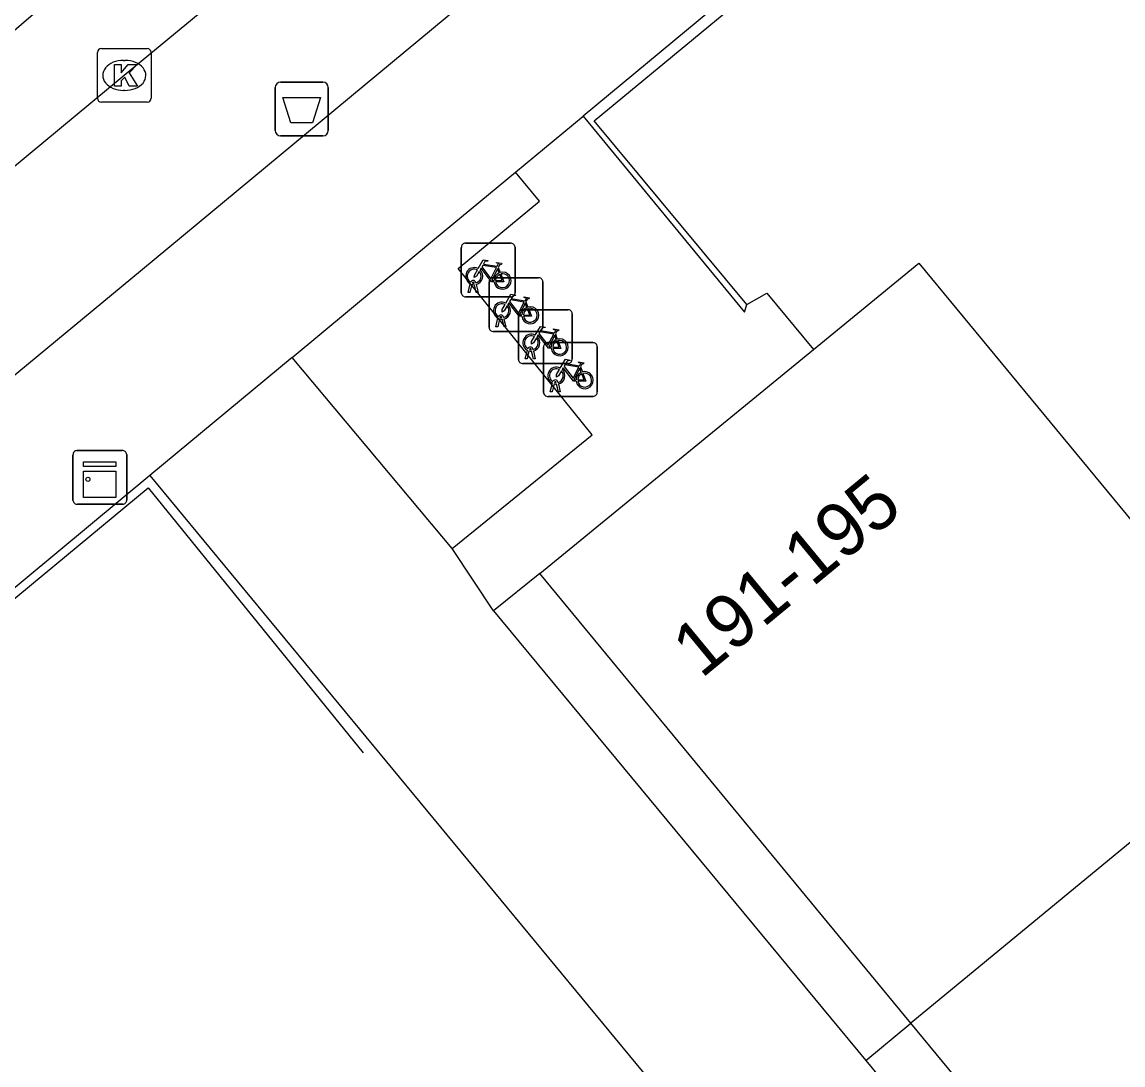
# Model space of a CAD drawing. Extents: x 162347 to 162868, y 381221 to 381813.
# Drawn here: x 162449.62 to 162470.1, y 381728.86 to 381748.27 of the extents above; entities that cross this region are included whole.
import ezdxf

# ---------------------------------------------------------------- set-up
doc = ezdxf.new("R2010")
doc.units = 0
for name, color, linetype in [('IMGEO_Afvalbak', 7, 'Continuous'), ('IMGEO_Fietsenrek', 7, 'Continuous'), ('IMGEO_Fietspad_open', 7, 'Continuous'), ('IMGEO_Hek', 7, 'Continuous'), ('IMGEO_Kast', 7, 'Continuous'), ('IMGEO_Kolk', 7, 'Continuous'), ('IMGEO_Pand', 7, 'Continuous'), ('IMGEO_Pand_nummerreeks', 7, 'Continuous'), ('IMGEO_Rijbaan_lokaal_open', 7, 'Continuous'), ('IMGEO_Voetpad_open', 7, 'Continuous')]:
    doc.layers.add(name, color=color, linetype=linetype)

msp = doc.modelspace()

# ---------------------------------------------------------------- linework, layer by layer
at = {"layer": 'IMGEO_Afvalbak'}
for p, q in [((162454.327, 381746.247), (162454.327, 381747.047)), ((162454.327, 381747.047), (162454.327, 381746.247)), ((162454.427, 381747.147), (162455.217, 381747.147)), ((162455.217, 381747.147), (162454.427, 381747.147)), ((162455.317, 381747.047), (162455.317, 381746.247)), ((162455.317, 381746.247), (162455.317, 381747.047)), ((162455.217, 381746.147), (162454.427, 381746.147)), ((162454.427, 381746.147), (162455.217, 381746.147))]:
    msp.add_line(p, q, dxfattribs=at)
msp.add_lwpolyline([(162454.47, 381746.861), (162455.174, 381746.861), (162455.025, 381746.391), (162454.619, 381746.391), (162454.47, 381746.861)], dxfattribs=at)
for centre, start, end in [((162454.427, 381747.047), 90, 180), ((162454.427, 381747.047), 90, 180), ((162455.217, 381747.047), 0, 90), ((162455.217, 381747.047), 360, 90), ((162454.427, 381746.247), 180, 270), ((162454.427, 381746.247), 180, 270), ((162455.217, 381746.247), 270, 0), ((162455.217, 381746.247), 270, 0)]:
    msp.add_arc(centre, 0.1, start, end, dxfattribs=at)
at = {"layer": 'IMGEO_Fietsenrek'}
for p, q in [((162457.792, 381743.226), (162457.792, 381744.067)), ((162457.792, 381744.067), (162457.792, 381743.226)), ((162457.867, 381744.151), (162458.708, 381744.151)), ((162458.708, 381744.151), (162457.867, 381744.151)), ((162458.792, 381744.076), (162458.792, 381743.235)), ((162458.792, 381743.235), (162458.792, 381744.076)), ((162458.479, 381743.7), (162458.515, 381743.605)), ((162457.919, 381743.235), (162457.958, 381743.395)), ((162457.988, 381743.383), (162457.953, 381743.235)), ((162458.03, 381743.407), (162458.029, 381743.411)), ((162458.071, 381743.235), (162458.037, 381743.377)), ((162458.061, 381743.418), (162458.062, 381743.411)), ((162458.069, 381743.381), (162458.104, 381743.235)), ((162458.308, 381742.583), (162458.308, 381743.424)), ((162458.308, 381743.424), (162458.308, 381742.583)), ((162458.383, 381743.508), (162459.224, 381743.508)), ((162459.224, 381743.508), (162458.383, 381743.508)), ((162459.308, 381743.433), (162459.308, 381742.592)), ((162459.308, 381742.592), (162459.308, 381743.433)), ((162458.717, 381743.151), (162457.876, 381743.151)), ((162457.876, 381743.151), (162458.717, 381743.151)), ((162457.953, 381743.235), (162457.919, 381743.235)), ((162458.104, 381743.235), (162458.071, 381743.235)), ((162458.995, 381743.057), (162459.031, 381742.962)), ((162458.435, 381742.592), (162458.474, 381742.752)), ((162458.504, 381742.74), (162458.469, 381742.592)), ((162458.546, 381742.764), (162458.545, 381742.768)), ((162458.577, 381742.775), (162458.578, 381742.768)), ((162458.855, 381741.987), (162458.855, 381742.828)), ((162458.855, 381742.828), (162458.855, 381741.987)), ((162458.93, 381742.912), (162459.771, 381742.912)), ((162459.771, 381742.912), (162458.93, 381742.912)), ((162459.855, 381742.837), (162459.855, 381741.996)), ((162459.855, 381741.996), (162459.855, 381742.837)), ((162458.469, 381742.592), (162458.435, 381742.592)), ((162458.587, 381742.592), (162458.553, 381742.734)), ((162458.585, 381742.738), (162458.62, 381742.592)), ((162458.62, 381742.592), (162458.587, 381742.592)), ((162459.233, 381742.508), (162458.392, 381742.508)), ((162458.392, 381742.508), (162459.233, 381742.508)), ((162459.542, 381742.461), (162459.578, 381742.366)), ((162458.982, 381741.996), (162459.021, 381742.156)), ((162459.051, 381742.144), (162459.016, 381741.996)), ((162459.093, 381742.168), (162459.092, 381742.172)), ((162459.134, 381741.996), (162459.1, 381742.138)), ((162459.124, 381742.179), (162459.125, 381742.172)), ((162459.132, 381742.142), (162459.167, 381741.996)), ((162459.321, 381741.374), (162459.321, 381742.215)), ((162459.321, 381742.215), (162459.321, 381741.374)), ((162459.396, 381742.299), (162460.237, 381742.299)), ((162460.237, 381742.299), (162459.396, 381742.299)), ((162460.321, 381742.224), (162460.321, 381741.383)), ((162460.321, 381741.383), (162460.321, 381742.224)), ((162459.016, 381741.996), (162458.982, 381741.996)), ((162459.167, 381741.996), (162459.134, 381741.996)), ((162459.78, 381741.912), (162458.939, 381741.912)), ((162458.939, 381741.912), (162459.78, 381741.912)), ((162460.008, 381741.848), (162460.044, 381741.753)), ((162459.448, 381741.383), (162459.487, 381741.543)), ((162459.517, 381741.531), (162459.482, 381741.383)), ((162459.559, 381741.555), (162459.558, 381741.559)), ((162459.6, 381741.383), (162459.566, 381741.525)), ((162459.59, 381741.566), (162459.591, 381741.559)), ((162459.598, 381741.529), (162459.633, 381741.383)), ((162459.482, 381741.383), (162459.448, 381741.383)), ((162459.633, 381741.383), (162459.6, 381741.383)), ((162460.246, 381741.299), (162459.405, 381741.299)), ((162459.405, 381741.299), (162460.246, 381741.299))]:
    msp.add_line(p, q, dxfattribs=at)
for points in [[(162458.105, 381743.677), (162458.2, 381743.841), (162458.286, 381743.827), (162458.288, 381743.818), (162458.232, 381743.807), (162458.205, 381743.762), (162458.461, 381743.721)], [(162458.461, 381743.721), (162458.486, 381743.77), (162458.48, 381743.774), (162458.457, 381743.778), (162458.445, 381743.785), (162458.444, 381743.788), (162458.446, 381743.793), (162458.541, 381743.778), (162458.543, 381743.768), (162458.533, 381743.755), (162458.521, 381743.749), (162458.507, 381743.755), (162458.479, 381743.7)], [(162458.126, 381743.625), (162458.074, 381743.535), (162458.034, 381743.51), (162458.035, 381743.557), (162458.09, 381743.651)], [(162458.401, 381743.433), (162458.351, 381743.433), (162458.16, 381743.684), (162458.141, 381743.652)], [(162458.448, 381743.696), (162458.191, 381743.737), (162458.174, 381743.708), (162458.341, 381743.488), (162458.448, 381743.696)], [(162458.496, 381743.598), (162458.466, 381743.675), (162458.357, 381743.457), (162458.4, 381743.457)], [(162458.43, 381743.457), (162458.55, 381743.456), (162458.506, 381743.57)], [(162458.526, 381743.577), (162458.581, 381743.432), (162458.431, 381743.432)], [(162458.621, 381743.034), (162458.716, 381743.198), (162458.802, 381743.184), (162458.804, 381743.175), (162458.748, 381743.164), (162458.721, 381743.119), (162458.977, 381743.078)], [(162458.977, 381743.078), (162459.002, 381743.127), (162458.996, 381743.131), (162458.973, 381743.135), (162458.961, 381743.142), (162458.96, 381743.145), (162458.962, 381743.15), (162459.057, 381743.135), (162459.059, 381743.125), (162459.049, 381743.112), (162459.037, 381743.106), (162459.023, 381743.112), (162458.995, 381743.057)], [(162458.642, 381742.982), (162458.59, 381742.892), (162458.55, 381742.867), (162458.551, 381742.914), (162458.606, 381743.008)], [(162458.917, 381742.79), (162458.867, 381742.79), (162458.676, 381743.041), (162458.657, 381743.009)], [(162458.964, 381743.053), (162458.707, 381743.094), (162458.69, 381743.065), (162458.857, 381742.845), (162458.964, 381743.053)], [(162459.012, 381742.955), (162458.982, 381743.032), (162458.873, 381742.814), (162458.916, 381742.814)], [(162458.946, 381742.814), (162459.066, 381742.813), (162459.022, 381742.927)], [(162459.042, 381742.934), (162459.097, 381742.789), (162458.947, 381742.789)], [(162459.168, 381742.438), (162459.263, 381742.602), (162459.349, 381742.588), (162459.351, 381742.579), (162459.295, 381742.568), (162459.268, 381742.523), (162459.524, 381742.482)], [(162459.524, 381742.482), (162459.549, 381742.531), (162459.543, 381742.535), (162459.52, 381742.539), (162459.508, 381742.546), (162459.507, 381742.549), (162459.509, 381742.554), (162459.604, 381742.539), (162459.606, 381742.529), (162459.596, 381742.516), (162459.584, 381742.51), (162459.57, 381742.516), (162459.542, 381742.461)], [(162459.189, 381742.386), (162459.137, 381742.296), (162459.097, 381742.271), (162459.098, 381742.318), (162459.153, 381742.412)], [(162459.464, 381742.194), (162459.414, 381742.194), (162459.223, 381742.445), (162459.204, 381742.413)], [(162459.511, 381742.457), (162459.254, 381742.498), (162459.237, 381742.469), (162459.404, 381742.249), (162459.511, 381742.457)], [(162459.559, 381742.359), (162459.529, 381742.436), (162459.42, 381742.218), (162459.463, 381742.218)], [(162459.493, 381742.218), (162459.613, 381742.217), (162459.569, 381742.331)], [(162459.589, 381742.338), (162459.644, 381742.193), (162459.494, 381742.193)], [(162459.634, 381741.825), (162459.729, 381741.989), (162459.815, 381741.975), (162459.817, 381741.966), (162459.761, 381741.955), (162459.734, 381741.91), (162459.99, 381741.869)], [(162459.99, 381741.869), (162460.015, 381741.918), (162460.009, 381741.922), (162459.986, 381741.926), (162459.974, 381741.933), (162459.973, 381741.936), (162459.975, 381741.941), (162460.07, 381741.926), (162460.072, 381741.916), (162460.062, 381741.903), (162460.05, 381741.897), (162460.036, 381741.903), (162460.008, 381741.848)], [(162459.655, 381741.773), (162459.603, 381741.683), (162459.563, 381741.658), (162459.564, 381741.705), (162459.619, 381741.799)], [(162459.93, 381741.581), (162459.88, 381741.581), (162459.689, 381741.832), (162459.67, 381741.8)], [(162459.977, 381741.844), (162459.72, 381741.885), (162459.703, 381741.856), (162459.87, 381741.636), (162459.977, 381741.844)], [(162460.025, 381741.746), (162459.995, 381741.823), (162459.886, 381741.605), (162459.929, 381741.605)], [(162459.959, 381741.605), (162460.079, 381741.604), (162460.035, 381741.718)], [(162460.055, 381741.725), (162460.11, 381741.58), (162459.96, 381741.58)]]:
    msp.add_lwpolyline(points, dxfattribs=at)
for centre, radius, start, end in [((162457.87, 381744.073), 0.0779, 92.4484, 184.2845), ((162457.87, 381744.073), 0.0779, 92.4484, 184.2845), ((162458.714, 381744.073), 0.0779, 2.4484, 94.2845), ((162458.714, 381744.073), 0.0779, 2.4484, 94.2845), ((162458.032, 381743.536), 0.159, 62.6766, 242.1369), ((162458.032, 381743.536), 0.129, 63.3192, 238.903), ((162458.032, 381743.536), 0.129, 283.6043, 43.4302), ((162458.032, 381743.536), 0.159, 283.5766, 46.6042), ((162458.559, 381743.452), 0.159, 113.3408, 178.3217), ((162458.559, 381743.452), 0.159, 187.0065, 105.7708), ((162458.559, 381743.452), 0.129, 113.923, 177.9556), ((162458.559, 381743.452), 0.129, 188.6715, 104.5883), ((162458.012, 381743.407), 0.0499, 12.8025, 158.6934), ((162458.032, 381743.536), 0.159, 253.9967, 271.7867), ((162458.012, 381743.407), 0.0174, 12.8025, 163.4502), ((162458.032, 381743.536), 0.129, 253.415, 269.0204), ((162458.386, 381743.43), 0.0779, 92.4484, 184.2845), ((162458.386, 381743.43), 0.0779, 92.4484, 184.2845), ((162459.23, 381743.43), 0.0779, 2.4484, 94.2845), ((162459.23, 381743.43), 0.0779, 2.4484, 94.2845), ((162457.87, 381743.229), 0.0779, 182.4484, 274.2845), ((162457.87, 381743.229), 0.0779, 182.4484, 274.2845), ((162458.714, 381743.229), 0.0779, 272.4484, 4.2845), ((162458.714, 381743.229), 0.0779, 272.4484, 4.2845), ((162458.548, 381742.893), 0.159, 62.6766, 242.1369), ((162458.548, 381742.893), 0.129, 63.3192, 238.903), ((162458.548, 381742.893), 0.129, 283.6043, 43.4302), ((162458.548, 381742.893), 0.159, 283.5766, 46.6042), ((162459.075, 381742.809), 0.159, 113.3408, 178.3217), ((162459.075, 381742.809), 0.159, 187.0065, 105.7708), ((162458.528, 381742.764), 0.0499, 12.8025, 158.6934), ((162458.548, 381742.893), 0.159, 253.9967, 271.7867), ((162458.528, 381742.764), 0.0174, 12.8025, 163.4502), ((162458.548, 381742.893), 0.129, 253.415, 269.0204), ((162458.933, 381742.834), 0.0779, 92.4484, 184.2845), ((162458.933, 381742.834), 0.0779, 92.4484, 184.2845), ((162459.075, 381742.809), 0.129, 113.923, 177.9556), ((162459.075, 381742.809), 0.129, 188.6715, 104.5883), ((162459.777, 381742.834), 0.0779, 2.4484, 94.2845), ((162459.777, 381742.834), 0.0779, 2.4484, 94.2845), ((162458.386, 381742.586), 0.0779, 182.4484, 274.2845), ((162458.386, 381742.586), 0.0779, 182.4484, 274.2845), ((162459.23, 381742.586), 0.0779, 272.4484, 4.2845), ((162459.23, 381742.586), 0.0779, 272.4484, 4.2845), ((162459.095, 381742.297), 0.159, 62.6766, 242.1369), ((162459.095, 381742.297), 0.129, 63.3192, 238.903), ((162459.095, 381742.297), 0.129, 283.6043, 43.4302), ((162459.095, 381742.297), 0.159, 283.5766, 46.6042), ((162459.622, 381742.213), 0.159, 113.3408, 178.3217), ((162459.622, 381742.213), 0.159, 187.0065, 105.7708), ((162459.622, 381742.213), 0.129, 113.923, 177.9556), ((162459.622, 381742.213), 0.129, 188.6715, 104.5883), ((162459.075, 381742.168), 0.0499, 12.8025, 158.6934), ((162459.095, 381742.297), 0.159, 253.9967, 271.7867), ((162459.075, 381742.168), 0.0174, 12.8025, 163.4502), ((162459.095, 381742.297), 0.129, 253.415, 269.0204), ((162459.399, 381742.221), 0.0779, 92.4484, 184.2845), ((162459.399, 381742.221), 0.0779, 92.4484, 184.2845), ((162460.243, 381742.221), 0.0779, 2.4484, 94.2845), ((162460.243, 381742.221), 0.0779, 2.4484, 94.2845), ((162458.933, 381741.99), 0.0779, 182.4484, 274.2845), ((162458.933, 381741.99), 0.0779, 182.4484, 274.2845), ((162459.777, 381741.99), 0.0779, 272.4484, 4.2845), ((162459.777, 381741.99), 0.0779, 272.4484, 4.2845), ((162459.561, 381741.684), 0.159, 62.6766, 242.1369), ((162459.561, 381741.684), 0.129, 63.3192, 238.903), ((162459.561, 381741.684), 0.129, 283.6043, 43.4302), ((162459.561, 381741.684), 0.159, 283.5766, 46.6042), ((162460.088, 381741.6), 0.159, 113.3408, 178.3217), ((162460.088, 381741.6), 0.159, 187.0065, 105.7708), ((162460.088, 381741.6), 0.129, 113.923, 177.9556), ((162460.088, 381741.6), 0.129, 188.6715, 104.5883), ((162459.541, 381741.555), 0.0499, 12.8025, 158.6934), ((162459.561, 381741.684), 0.159, 253.9967, 271.7867), ((162459.541, 381741.555), 0.0174, 12.8025, 163.4502), ((162459.561, 381741.684), 0.129, 253.415, 269.0204), ((162459.399, 381741.377), 0.0779, 182.4484, 274.2845), ((162459.399, 381741.377), 0.0779, 182.4484, 274.2845), ((162460.243, 381741.377), 0.0779, 272.4484, 4.2845), ((162460.243, 381741.377), 0.0779, 272.4484, 4.2845)]:
    msp.add_arc(centre, radius, start, end, dxfattribs=at)
at = {"layer": 'IMGEO_Fietspad_open'}
msp.add_lwpolyline([(162455.794, 381750.801), (162451.521, 381747.272), (162447.905, 381744.275), (162433.442, 381732.29), (162428.876, 381728.513), (162426.389, 381726.442), (162426.314, 381726.37)], dxfattribs=at)
at = {"layer": 'IMGEO_Hek'}
for points in [[(162463.106, 381743.006), (162460.263, 381746.426), (162477.364, 381760.553), (162481.17, 381755.868)], [(162437.475, 381721.871), (162434.659, 381725.263), (162451.967, 381739.596), (162455.968, 381734.665)]]:
    msp.add_lwpolyline(points, dxfattribs=at)
at = {"layer": 'IMGEO_Kast'}
for p, q in [((162450.641, 381740.291), (162451.482, 381740.291)), ((162451.482, 381740.291), (162450.641, 381740.291)), ((162450.566, 381739.366), (162450.566, 381740.207)), ((162450.566, 381740.207), (162450.566, 381739.366)), ((162451.566, 381740.216), (162451.566, 381739.375)), ((162451.566, 381739.375), (162451.566, 381740.216)), ((162451.491, 381739.291), (162450.65, 381739.291)), ((162450.65, 381739.291), (162451.491, 381739.291))]:
    msp.add_line(p, q, dxfattribs=at)
for points in [[(162450.761, 381740.081), (162451.361, 381740.081), (162451.361, 381739.996), (162450.761, 381739.996), (162450.761, 381740.081)], [(162450.761, 381739.906), (162451.361, 381739.906), (162451.361, 381739.417), (162450.761, 381739.417), (162450.761, 381739.906)]]:
    msp.add_lwpolyline(points, dxfattribs=at)
msp.add_circle((162450.845, 381739.755), 0.0377, dxfattribs=at)
for centre, start, end in [((162450.644, 381740.213), 92.4484, 184.2845), ((162450.644, 381740.213), 92.4484, 184.2845), ((162451.488, 381740.213), 2.4484, 94.2845), ((162451.488, 381740.213), 2.4484, 94.2845), ((162450.644, 381739.369), 182.4484, 274.2845), ((162450.644, 381739.369), 182.4484, 274.2845), ((162451.488, 381739.369), 272.4484, 4.2845), ((162451.488, 381739.369), 272.4484, 4.2845)]:
    msp.add_arc(centre, 0.0779, start, end, dxfattribs=at)
at = {"layer": 'IMGEO_Kolk'}
for p, q in [((162451.02, 381746.846), (162451.02, 381747.698)), ((162451.095, 381747.772), (162451.947, 381747.772)), ((162452.021, 381747.698), (162452.021, 381746.846)), ((162451.508, 381747.552), (162451.533, 381747.552)), ((162451.531, 381746.992), (162451.506, 381746.992)), ((162451.947, 381746.772), (162451.095, 381746.772))]:
    msp.add_line(p, q, dxfattribs=at)
for points in [[(162451.02, 381746.846), (162451.02, 381747.698)], [(162451.095, 381747.772), (162451.947, 381747.772)], [(162452.021, 381747.698), (162452.021, 381746.846)], [(162451.341, 381747.472), (162451.464, 381747.472), (162451.464, 381747.321), (162451.594, 381747.472), (162451.758, 381747.472), (162451.612, 381747.321), (162451.765, 381747.072), (162451.613, 381747.072), (162451.528, 381747.236), (162451.464, 381747.169), (162451.464, 381747.072), (162451.341, 381747.072), (162451.341, 381747.472)], [(162451.947, 381746.772), (162451.095, 381746.772)]]:
    msp.add_lwpolyline(points, dxfattribs=at)
for centre, start, end in [((162451.097, 381747.696), 91.552, 178.448), ((162451.097, 381747.696), 91.552, 178.448), ((162451.945, 381747.696), 1.552, 88.448), ((162451.945, 381747.696), 1.552, 88.448), ((162451.097, 381746.848), 181.552, 268.448), ((162451.097, 381746.848), 181.552, 268.448), ((162451.945, 381746.848), 271.552, 358.448), ((162451.945, 381746.848), 271.552, 358.448)]:
    msp.add_arc(centre, 0.0765, start, end, dxfattribs=at)
for centre, major_axis, ratio, start_param, end_param in [((162451.507, 381747.272), (-0.387, 0.002), 0.722429, 4.712389, 7.853982), ((162451.532, 381747.272), (-0.39, 0.002), 0.717154, 1.570796, 4.712389)]:
    msp.add_ellipse(centre, major_axis=major_axis, ratio=ratio, start_param=start_param, end_param=end_param, dxfattribs=at)
at = {"layer": 'IMGEO_Pand'}
for points in [[(162464.348, 381742.174), (162466.307, 381743.777), (162473.193, 381735.435)], [(162459.252, 381738.006), (162464.348, 381742.174)], [(162466.159, 381729.634), (162459.252, 381738.006)], [(162473.193, 381735.435), (162466.159, 381729.634)], [(162468.393, 381726.927), (162466.159, 381729.634)]]:
    msp.add_lwpolyline(points, dxfattribs=at)
at = {"layer": 'IMGEO_Rijbaan_lokaal_open'}
msp.add_lwpolyline([(162453.794, 381753.188), (162450.654, 381749.123), (162425.365, 381727.418)], dxfattribs=at)
at = {"layer": 'IMGEO_Voetpad_open'}
for points in [[(162426.314, 381726.37), (162428.207, 381724.094), (162451.823, 381743.637), (162459.348, 381749.88), (162485.569, 381771.54), (162486.346, 381772.165), (162499.033, 381781.642), (162500.475, 381782.734), (162498.716, 381785.09)], [(162477.365, 381760.866), (162460.058, 381746.513)], [(162458.802, 381745.471), (162460.058, 381746.513)], [(162460.058, 381746.513), (162463.062, 381742.868), (162463.106, 381743.006), (162463.476, 381743.219), (162464.348, 381742.174)], [(162454.645, 381742.024), (162457.296, 381744.222), (162458.802, 381745.471)], [(162457.62, 381738.466), (162460.226, 381740.585), (162457.735, 381743.677), (162459.249, 381744.932), (162458.802, 381745.471)], [(162454.645, 381742.024), (162451.996, 381739.827)], [(162457.62, 381738.466), (162454.645, 381742.024)], [(162451.996, 381739.827), (162449.119, 381737.441), (162434.479, 381725.379)], [(162451.996, 381739.827), (162461.541, 381728.274)], [(162458.388, 381737.311), (162457.62, 381738.466)], [(162459.252, 381738.006), (162458.388, 381737.311)], [(162458.388, 381737.311), (162465.316, 381728.939)], [(162465.316, 381728.939), (162466.159, 381729.634)], [(162465.316, 381728.939), (162467.553, 381726.234)]]:
    msp.add_lwpolyline(points, dxfattribs=at)

# ---------------------------------------------------------------- texts
at = {"layer": 'IMGEO_Pand_nummerreeks'}
msp.add_text('191-195', height=1, rotation=39.5235, dxfattribs=at).set_placement((162462.257, 381736.034))

doc.saveas('drawing.dxf')
